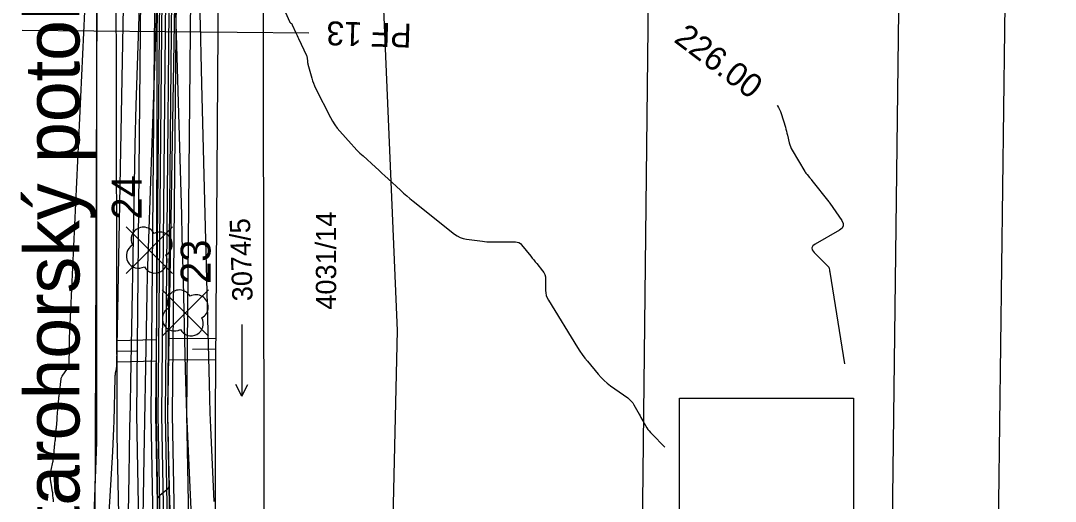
# Model space of a CAD drawing. Extents: x -534410 to -534262, y -1190162 to -1189584.
# Drawn here: x -534372.62 to -534329.29, y -1189850.35 to -1189830.22 of the extents above; entities that cross this region are included whole.
import ezdxf

# ---------------------------------------------------------------- set-up
doc = ezdxf.new("R2010")
doc.units = 0
for name, color, linetype in [('30', 7, 'Continuous'), ('31', 7, 'Continuous'), ('40', 7, 'Continuous'), ('_linie', 7, 'Continuous'), ('_N_osa', 7, 'Continuous'), ('_N_tenká', 7, 'Continuous'), ('_N_tenká_velmi', 7, 'Continuous'), ('_N_text', 7, 'Continuous'), ('_přístup', 7, 'Continuous'), ('_tenka', 7, 'Continuous'), ('_velmi_tenka', 7, 'Continuous'), ('Default', 7, 'Continuous'), ('Hranice parcel', 7, 'Continuous'), ('Parcelní čísla', 7, 'Continuous'), ('Pop  PČ popisy', 7, 'Continuous'), ('Značky kultur', 7, 'Continuous')]:
    doc.layers.add(name, color=color, linetype=linetype)

msp = doc.modelspace()

# ---------------------------------------------------------------- linework, layer by layer
at = {"layer": '30'}
for points in [[(-534371.244, -1189850.375), (-534371.248, -1189850.341), (-534371.252, -1189850.306), (-534371.255, -1189850.272), (-534371.258, -1189850.238), (-534371.271, -1189850.1), (-534371.275, -1189850.066), (-534371.279, -1189850.032), (-534371.284, -1189849.997), (-534371.29, -1189849.963), (-534371.354, -1189849.6), (-534371.361, -1189849.554), (-534371.366, -1189849.509), (-534371.369, -1189849.463), (-534371.369, -1189849.417), (-534371.367, -1189849.233), (-534371.366, -1189849.187), (-534371.362, -1189849.141), (-534371.356, -1189849.095), (-534371.347, -1189849.05), (-534371.276, -1189848.71), (-534371.269, -1189848.675), (-534371.263, -1189848.638), (-534371.258, -1189848.602), (-534371.253, -1189848.566), (-534371.238, -1189848.42), (-534371.234, -1189848.384), (-534371.23, -1189848.347), (-534371.227, -1189848.311), (-534371.224, -1189848.274), (-534371.205, -1189848.054), (-534371.202, -1189848.024), (-534371.199, -1189847.994), (-534371.195, -1189847.964), (-534371.191, -1189847.934), (-534371.174, -1189847.815), (-534371.17, -1189847.785), (-534371.166, -1189847.755), (-534371.163, -1189847.725), (-534371.161, -1189847.695), (-534371.143, -1189847.465), (-534371.139, -1189847.416), (-534371.136, -1189847.368), (-534371.132, -1189847.319), (-534371.128, -1189847.271), (-534371.101, -1189846.933), (-534371.1, -1189846.923), (-534371.1, -1189846.914), (-534371.099, -1189846.905), (-534371.099, -1189846.896), (-534371.1, -1189846.859), (-534371.1, -1189846.85), (-534371.099, -1189846.841), (-534371.099, -1189846.832), (-534371.098, -1189846.823), (-534371.067, -1189846.499), (-534371.061, -1189846.444), (-534371.056, -1189846.388), (-534371.051, -1189846.333), (-534371.046, -1189846.277), (-534371.02, -1189845.971), (-534371.019, -1189845.957), (-534371.017, -1189845.943), (-534371.015, -1189845.93), (-534371.013, -1189845.916), (-534371.002, -1189845.86), (-534371, -1189845.846), (-534370.998, -1189845.833), (-534370.996, -1189845.819), (-534370.994, -1189845.805), (-534370.96, -1189845.471), (-534370.957, -1189845.44), (-534370.953, -1189845.409), (-534370.949, -1189845.378), (-534370.945, -1189845.347), (-534370.928, -1189845.223), (-534370.922, -1189845.192), (-534370.913, -1189845.163), (-534370.9, -1189845.135), (-534370.884, -1189845.109), (-534370.661, -1189844.787), (-534370.635, -1189844.744), (-534370.616, -1189844.699), (-534370.604, -1189844.651), (-534370.599, -1189844.601), (-534370.59, -1189844.359), (-534370.588, -1189844.327), (-534370.588, -1189844.294), (-534370.587, -1189844.262), (-534370.586, -1189844.229), (-534370.584, -1189844.067), (-534370.583, -1189844.035), (-534370.583, -1189844.003), (-534370.581, -1189843.94), (-534370.58, -1189843.908), (-534370.579, -1189843.876), (-534370.577, -1189843.711), (-534370.576, -1189843.646), (-534370.575, -1189843.58), (-534370.573, -1189843.403), (-534370.573, -1189843.376), (-534370.572, -1189843.349), (-534370.571, -1189843.296), (-534370.571, -1189843.282), (-534370.57, -1189843.269), (-534370.57, -1189843.255), (-534370.569, -1189843.242), (-534369.518, -1189820.88)], [(-534369.971, -1189897.16), (-534368.36, -1189871.02), (-534368.275, -1189869.436), (-534368.214, -1189867.85), (-534368.178, -1189866.264), (-534368.167, -1189864.676), (-534368.175, -1189857.116), (-534368.173, -1189856.134), (-534368.168, -1189855.152), (-534368.158, -1189854.17), (-534368.144, -1189853.188), (-534368.08, -1189849.26), (-534368.063, -1189848.277), (-534368.046, -1189847.295), (-534368.029, -1189846.313), (-534368.011, -1189845.331), (-534367.857, -1189837.063), (-534367.823, -1189835.407), (-534367.782, -1189833.752), (-534367.734, -1189832.096), (-534367.679, -1189830.441), (-534367.447, -1189823.822)], [(-534365.145, -1189829.164), (-534365.111, -1189830.395), (-534365.079, -1189831.626), (-534365.048, -1189832.857), (-534364.733, -1189845.414), (-534364.716, -1189846.032), (-534364.696, -1189846.65), (-534364.672, -1189847.268), (-534364.645, -1189847.886), (-534364.532, -1189850.357)], [(-534340.948, -1189833.761), (-534340.933, -1189833.783), (-534340.884, -1189833.858), (-534340.841, -1189833.936), (-534340.805, -1189834.018), (-534340.776, -1189834.102), (-534340.597, -1189834.684), (-534340.573, -1189834.764), (-534340.551, -1189834.845), (-534340.53, -1189834.927), (-534340.51, -1189835.008), (-534340.436, -1189835.336), (-534340.414, -1189835.416), (-534340.386, -1189835.495), (-534340.352, -1189835.571), (-534340.312, -1189835.644), (-534339.784, -1189836.536), (-534339.763, -1189836.57), (-534339.74, -1189836.603), (-534339.716, -1189836.634), (-534339.691, -1189836.665), (-534339.587, -1189836.785), (-534339.561, -1189836.815), (-534339.536, -1189836.845), (-534339.511, -1189836.876), (-534339.486, -1189836.907), (-534338.782, -1189837.804), (-534338.768, -1189837.821), (-534338.754, -1189837.839), (-534338.747, -1189837.848), (-534338.74, -1189837.857), (-534338.233, -1189838.595), (-534338.174, -1189838.714), (-534338.17, -1189838.819), (-534338.22, -1189838.913), (-534338.324, -1189838.993), (-534339.35, -1189839.574), (-534339.448, -1189839.65), (-534339.489, -1189839.733), (-534339.472, -1189839.825), (-534339.397, -1189839.924), (-534338.809, -1189840.513), (-534338.795, -1189840.528), (-534338.784, -1189840.545), (-534338.776, -1189840.564), (-534338.77, -1189840.584), (-534338.754, -1189840.666), (-534338.75, -1189840.687), (-534338.746, -1189840.708), (-534338.742, -1189840.729), (-534338.739, -1189840.749), (-534338.124, -1189844.595)], [(-534364.785, -1189884.896), (-534366.41, -1189849.75), (-534366.411, -1189849.736), (-534366.415, -1189849.731), (-534366.419, -1189849.735), (-534366.426, -1189849.747), (-534366.455, -1189849.813), (-534366.463, -1189849.829), (-534366.473, -1189849.844), (-534366.484, -1189849.857), (-534366.498, -1189849.869), (-534366.792, -1189850.108), (-534366.839, -1189850.154), (-534366.873, -1189850.208), (-534366.894, -1189850.267), (-534366.902, -1189850.333), (-534367.168, -1189866.532), (-534367.207, -1189869.255), (-534367.234, -1189871.978), (-534367.249, -1189874.701), (-534367.252, -1189877.424), (-534367.219, -1189912.738)]]:
    msp.add_lwpolyline(points, dxfattribs=at)
at = {"layer": '31'}
for points in [[(-534364.093, -1189824.142), (-534361.369, -1189830.256), (-534361.362, -1189830.269), (-534361.354, -1189830.282), (-534361.344, -1189830.293), (-534361.333, -1189830.303), (-534361.284, -1189830.342), (-534361.273, -1189830.352), (-534361.263, -1189830.364), (-534361.254, -1189830.376), (-534361.247, -1189830.39), (-534361.098, -1189830.724), (-534361.071, -1189830.784), (-534361.044, -1189830.844), (-534361.016, -1189830.904), (-534360.988, -1189830.964), (-534360.656, -1189831.676), (-534360.644, -1189831.704), (-534360.635, -1189831.733), (-534360.629, -1189831.762), (-534360.625, -1189831.793), (-534360.616, -1189831.915), (-534360.612, -1189831.946), (-534360.608, -1189831.976), (-534360.602, -1189832.006), (-534360.595, -1189832.036), (-534360.434, -1189832.628), (-534360.402, -1189832.735), (-534360.365, -1189832.84), (-534360.322, -1189832.944), (-534360.273, -1189833.045), (-534359.648, -1189834.273), (-534359.563, -1189834.427), (-534359.468, -1189834.576), (-534359.365, -1189834.717), (-534359.252, -1189834.853), (-534358.781, -1189835.383), (-534358.662, -1189835.514), (-534358.539, -1189835.641), (-534358.413, -1189835.765), (-534358.284, -1189835.885), (-534357.76, -1189836.361), (-534357.629, -1189836.481), (-534357.499, -1189836.6), (-534357.369, -1189836.72), (-534357.239, -1189836.84), (-534356.722, -1189837.323), (-534356.591, -1189837.442), (-534356.458, -1189837.559), (-534356.323, -1189837.673), (-534356.186, -1189837.784), (-534354.456, -1189839.157), (-534354.341, -1189839.237), (-534354.218, -1189839.299), (-534354.088, -1189839.344), (-534353.95, -1189839.372), (-534353.281, -1189839.461), (-534353.192, -1189839.472), (-534353.102, -1189839.479), (-534353.013, -1189839.483), (-534352.923, -1189839.485), (-534352.464, -1189839.485), (-534352.223, -1189839.485), (-534351.903, -1189839.485), (-534351.827, -1189839.493), (-534351.758, -1189839.516), (-534351.697, -1189839.555), (-534351.643, -1189839.61), (-534351.261, -1189840.087), (-534351.2, -1189840.163), (-534351.138, -1189840.239), (-534351.076, -1189840.315), (-534351.013, -1189840.391), (-534350.763, -1189840.693), (-534350.709, -1189840.772), (-534350.67, -1189840.856), (-534350.646, -1189840.945), (-534350.638, -1189841.041), (-534350.638, -1189841.516), (-534350.631, -1189841.626), (-534350.609, -1189841.732), (-534350.573, -1189841.833), (-534350.521, -1189841.931), (-534349.301, -1189843.914), (-534349.206, -1189844.064), (-534349.105, -1189844.209), (-534348.999, -1189844.351), (-534348.888, -1189844.489), (-534348.432, -1189845.034), (-534348.315, -1189845.166), (-534348.189, -1189845.29), (-534348.056, -1189845.405), (-534347.916, -1189845.512), (-534347.202, -1189846.021), (-534347.124, -1189846.084), (-534347.054, -1189846.153), (-534346.992, -1189846.231), (-534346.939, -1189846.315), (-534346.725, -1189846.7), (-534346.685, -1189846.772), (-534346.644, -1189846.844), (-534346.603, -1189846.916), (-534346.562, -1189846.987), (-534346.396, -1189847.272), (-534346.352, -1189847.341), (-534346.304, -1189847.408), (-534346.252, -1189847.471), (-534346.196, -1189847.531), (-534345.645, -1189848.085)], [(-534371.625, -1189891.598), (-534370.83, -1189881.739), (-534370.701, -1189880.087), (-534370.581, -1189878.435), (-534370.47, -1189876.783), (-534370.367, -1189875.13), (-534368.767, -1189848.262), (-534368.749, -1189847.944), (-534368.734, -1189847.627), (-534368.723, -1189847.309), (-534368.714, -1189846.991), (-534368.672, -1189845.178), (-534368.67, -1189845.131), (-534368.666, -1189845.084), (-534368.659, -1189845.038), (-534368.651, -1189844.991), (-534368.615, -1189844.806), (-534368.607, -1189844.76), (-534368.601, -1189844.714), (-534368.597, -1189844.667), (-534368.595, -1189844.62), (-534368.288, -1189828.137)], [(-534364.605, -1189869.948), (-534365.584, -1189848.548), (-534365.624, -1189847.62), (-534365.659, -1189846.693), (-534365.689, -1189845.766), (-534365.715, -1189844.838), (-534365.808, -1189841.128), (-534365.831, -1189840.2), (-534365.856, -1189839.273), (-534365.881, -1189838.345), (-534365.907, -1189837.418), (-534366.164, -1189828.418)], [(-534366.924, -1189829.286), (-534367.277, -1189839.352), (-534367.303, -1189840.115), (-534367.325, -1189840.877), (-534367.343, -1189841.64), (-534367.359, -1189842.403), (-534367.416, -1189845.454), (-534367.43, -1189846.216), (-534367.444, -1189846.979), (-534367.457, -1189847.742), (-534367.469, -1189848.505), (-534367.649, -1189859.418), (-534367.678, -1189861.492), (-534367.699, -1189863.565), (-534367.71, -1189865.638), (-534367.713, -1189867.712), (-534367.696, -1189886.193), (-534367.71, -1189888.284), (-534367.757, -1189890.373)]]:
    msp.add_lwpolyline(points, dxfattribs=at)
at = {"layer": '_linie'}
for points in [[(-534366.12, -1189620.81), (-534364.52, -1189627.2), (-534365.69, -1189653.8), (-534366.76, -1189684.81), (-534368.14, -1189748.73), (-534368.38, -1189779.14), (-534368.65, -1189820.64), (-534368.59, -1189847.58), (-534367.2, -1189913.8)], [(-534363.12, -1189621.02), (-534362.79, -1189621.58), (-534361.82, -1189627.79), (-534363.46, -1189653.55), (-534365.47, -1189684.77), (-534366.65, -1189748.83), (-534366.75, -1189779.47), (-534366.9, -1189820.47), (-534366.95, -1189846.72), (-534366.338, -1189888.804), (-534363.85, -1189911.95), (-534357.07, -1189929.19), (-534352.334, -1189940.856)], [(-534359.03, -1189621.26), (-534359.41, -1189621.83), (-534360.84, -1189627.76), (-534362.92, -1189653.56), (-534364.64, -1189685), (-534365.94, -1189748.9), (-534366.02, -1189779.52), (-534366.03, -1189820.5), (-534366.48, -1189846.73), (-534365.511, -1189888.873), (-534362.72, -1189912.12), (-534356.62, -1189928.64), (-534351.589, -1189940.594)]]:
    msp.add_lwpolyline(points, dxfattribs=at)
at = {"layer": '_N_osa'}
msp.add_lwpolyline([(-534351.95, -1189940.722), (-534356.845, -1189928.915), (-534363.285, -1189912.035), (-534365.925, -1189888.838), (-534366.715, -1189846.725), (-534366.465, -1189820.485), (-534366.385, -1189779.495), (-534366.295, -1189748.865), (-534365.055, -1189684.885), (-534363.19, -1189653.555), (-534361.333, -1189627.822)], dxfattribs=at)
at = {"layer": '_N_tenká'}
for points in [[(-534352.92, -1189941.124), (-534357.821, -1189929.303), (-534364.313, -1189912.285), (-534366.973, -1189888.908), (-534367.765, -1189846.73), (-534367.515, -1189820.479), (-534367.435, -1189779.492), (-534367.345, -1189748.853), (-534366.104, -1189684.844), (-534364.238, -1189653.486), (-534362.424, -1189628.352), (-534361.782, -1189627.792)], [(-534350.98, -1189940.319), (-534355.869, -1189928.527), (-534362.257, -1189911.785), (-534364.876, -1189888.769), (-534365.665, -1189846.72), (-534365.415, -1189820.491), (-534365.335, -1189779.498), (-534365.245, -1189748.877), (-534364.006, -1189684.926), (-534362.142, -1189653.624), (-534360.329, -1189628.488), (-534360.884, -1189627.851)]]:
    msp.add_lwpolyline(points, dxfattribs=at)
at = {"layer": '_N_tenká_velmi'}
for points in [[(-534352.366, -1189940.894), (-534357.263, -1189929.081), (-534363.726, -1189912.142), (-534366.374, -1189888.868), (-534367.165, -1189846.727), (-534366.915, -1189820.482), (-534366.835, -1189779.494), (-534366.745, -1189748.86), (-534365.505, -1189684.867), (-534363.639, -1189653.525), (-534361.782, -1189627.792)], [(-534352.181, -1189940.817), (-534357.077, -1189929.007), (-534363.53, -1189912.095), (-534366.174, -1189888.855), (-534366.965, -1189846.726), (-534366.715, -1189820.484), (-534366.635, -1189779.494), (-534366.545, -1189748.862), (-534365.305, -1189684.875), (-534363.439, -1189653.539), (-534361.583, -1189627.805)], [(-534352.089, -1189940.779), (-534356.984, -1189928.97), (-534363.432, -1189912.071), (-534366.074, -1189888.848), (-534366.865, -1189846.726), (-534366.615, -1189820.484), (-534366.535, -1189779.495), (-534366.445, -1189748.863), (-534365.205, -1189684.879), (-534363.34, -1189653.545), (-534361.483, -1189627.812)], [(-534351.812, -1189940.664), (-534356.706, -1189928.86), (-534363.138, -1189911.999), (-534365.775, -1189888.828), (-534366.565, -1189846.724), (-534366.315, -1189820.486), (-534366.235, -1189779.495), (-534366.145, -1189748.867), (-534364.905, -1189684.891), (-534363.04, -1189653.565), (-534361.184, -1189627.831)], [(-534351.719, -1189940.626), (-534356.613, -1189928.823), (-534363.04, -1189911.975), (-534365.675, -1189888.822), (-534366.465, -1189846.724), (-534366.215, -1189820.486), (-534366.135, -1189779.496), (-534366.045, -1189748.868), (-534364.805, -1189684.895), (-534362.941, -1189653.571), (-534361.084, -1189627.838)], [(-534351.534, -1189940.549), (-534356.427, -1189928.749), (-534362.844, -1189911.928), (-534365.475, -1189888.808), (-534366.265, -1189846.723), (-534366.015, -1189820.488), (-534365.935, -1189779.496), (-534365.845, -1189748.87), (-534364.605, -1189684.903), (-534362.741, -1189653.585), (-534360.884, -1189627.851)]]:
    msp.add_lwpolyline(points, dxfattribs=at)
at = {"layer": '_N_text'}
msp.add_lwpolyline([(-534360.562, -1189830.746), (-534372.562, -1189830.632)], dxfattribs=at)
msp.add_lwpolyline([(-534345.025, -1189888.22), (-534345.025, -1189846.037), (-534337.749, -1189846.037), (-534337.749, -1189888.22)], close=True, dxfattribs=at)
at = {"layer": '_přístup'}
for p, q in [((-534366.267, -1189840.803), (-534368.213, -1189838.857)), ((-534368.213, -1189840.803), (-534366.267, -1189838.857)), ((-534364.757, -1189843.433), (-534366.703, -1189841.487)), ((-534366.703, -1189843.433), (-534364.757, -1189841.487))]:
    msp.add_line(p, q, dxfattribs=at)
for centre in [(-534367.24, -1189839.83), (-534365.73, -1189842.46)]:
    msp.add_circle(centre, 0.000512, dxfattribs=at)
for centre, start, end in [((-534367.485, -1189839.381), 28.6209, 208.6209), ((-534366.791, -1189839.585), 298.6209, 118.6209), ((-534367.689, -1189840.075), 118.6209, 298.6209), ((-534366.995, -1189840.279), 208.6209, 28.6209), ((-534365.975, -1189842.011), 28.6209, 208.6209), ((-534365.281, -1189842.215), 298.6209, 118.6209), ((-534366.179, -1189842.705), 118.6209, 298.6209), ((-534365.485, -1189842.909), 208.6209, 28.6209)]:
    msp.add_arc(centre, 0.512, start, end, dxfattribs=at)
at = {"layer": '_tenka'}
for points in [[(-534349.13, -1189939.73), (-534354.63, -1189926.96), (-534362.03, -1189907.65), (-534364.521, -1189888.74), (-534364.47, -1189846.64), (-534364.29, -1189820.63), (-534364.22, -1189780.69), (-534363.18, -1189749.38), (-534362.5, -1189685.39), (-534360.27, -1189651.6), (-534357.03, -1189627.34), (-534354.77, -1189620.37)], [(-534366.12, -1189620.81), (-534364.52, -1189627.2), (-534365.69, -1189653.8), (-534366.76, -1189684.81), (-534368.14, -1189748.73), (-534368.38, -1189779.14), (-534368.65, -1189820.64), (-534368.59, -1189847.58), (-534367.2, -1189913.8)], [(-534366.12, -1189620.81), (-534364.52, -1189627.2), (-534365.69, -1189653.8), (-534366.76, -1189684.81), (-534368.14, -1189748.73), (-534368.38, -1189779.14), (-534368.65, -1189820.64), (-534368.59, -1189847.58), (-534367.2, -1189913.8)], [(-534363.12, -1189621.02), (-534362.79, -1189621.58), (-534361.82, -1189627.79), (-534363.46, -1189653.55), (-534365.47, -1189684.77), (-534366.65, -1189748.83), (-534366.75, -1189779.47), (-534366.9, -1189820.47), (-534366.95, -1189846.72), (-534366.338, -1189888.804), (-534363.85, -1189911.95), (-534357.07, -1189929.19), (-534352.334, -1189940.856)], [(-534363.12, -1189621.02), (-534362.79, -1189621.58), (-534361.82, -1189627.79), (-534363.46, -1189653.55), (-534365.47, -1189684.77), (-534366.65, -1189748.83), (-534366.75, -1189779.47), (-534366.9, -1189820.47), (-534366.95, -1189846.72), (-534366.338, -1189888.804), (-534363.85, -1189911.95), (-534357.07, -1189929.19), (-534352.334, -1189940.856)], [(-534359.03, -1189621.26), (-534359.41, -1189621.83), (-534360.84, -1189627.76), (-534362.92, -1189653.56), (-534364.64, -1189685), (-534365.94, -1189748.9), (-534366.02, -1189779.52), (-534366.03, -1189820.5), (-534366.48, -1189846.73), (-534365.511, -1189888.873), (-534362.72, -1189912.12), (-534356.62, -1189928.64), (-534351.589, -1189940.594)], [(-534359.03, -1189621.26), (-534359.41, -1189621.83), (-534360.84, -1189627.76), (-534362.92, -1189653.56), (-534364.64, -1189685), (-534365.94, -1189748.9), (-534366.02, -1189779.52), (-534366.03, -1189820.5), (-534366.48, -1189846.73), (-534365.511, -1189888.873), (-534362.72, -1189912.12), (-534356.62, -1189928.64), (-534351.589, -1189940.594)], [(-534368.65, -1189626.81), (-534368.65, -1189626.81), (-534367.31, -1189654.04), (-534367.67, -1189685.23), (-534369.56, -1189748.93), (-534369.48, -1189778.6), (-534369.45, -1189820.62), (-534369.45, -1189847.87), (-534371.206, -1189896.071), (-534372.39, -1189914.47)]]:
    msp.add_lwpolyline(points, dxfattribs=at)
at = {"layer": '_velmi_tenka'}
for p, q in [((-534364.455, -1189843.532), (-534366.402, -1189843.546)), ((-534368.609, -1189843.616), (-534366.956, -1189843.574)), ((-534364.452, -1189843.982), (-534365.425, -1189843.989)), ((-534368.598, -1189844.066), (-534367.771, -1189844.045)), ((-534364.448, -1189844.432), (-534366.396, -1189844.446)), ((-534368.586, -1189844.516), (-534366.933, -1189844.473))]:
    msp.add_line(p, q, dxfattribs=at)
at = {"layer": 'Default'}
msp.add_line((-534369.45, -1189820.62), (-534369.45, -1189847.87), dxfattribs=at)
msp.add_lwpolyline([(-534349.13, -1189939.73), (-534354.63, -1189926.96), (-534362.03, -1189907.65), (-534364.521, -1189888.74), (-534364.47, -1189846.64), (-534364.29, -1189820.63), (-534364.22, -1189780.69), (-534363.18, -1189749.38), (-534362.5, -1189685.39), (-534360.27, -1189651.6), (-534357.03, -1189627.34), (-534354.77, -1189620.37)], dxfattribs=at)
at = {"layer": 'Hranice parcel'}
msp.add_line((-534369.75, -1189908.47), (-534369.38, -1189820.8), dxfattribs=at)
for points in [[(-534347.07, -1189935.15), (-534347.12, -1189900.1), (-534346.3, -1189826.77), (-534344.77, -1189736.43), (-534342.85, -1189658.07), (-534338.334, -1189584.47)], [(-534338.84, -1189942.48), (-534336.49, -1189881.83), (-534334.78, -1189743.85), (-534331.25, -1189619.05), (-534329.563, -1189584.47)], [(-534334.89, -1189942.46), (-534332.03, -1189880.06), (-534330.32, -1189744.92), (-534329.292, -1189689.47)], [(-534359.48, -1189697.97), (-534362.6, -1189764.35), (-534362.34, -1189901.56)], [(-534359.48, -1189697.97), (-534360.42, -1189747.8), (-534359.17, -1189788.69), (-534356.86, -1189843.2), (-534358.53, -1189915.98)]]:
    msp.add_lwpolyline(points, dxfattribs=at)
at = {"layer": 'Značky kultur'}
for p, q in [((-534363.36, -1189842.944), (-534363.36, -1189845.944)), ((-534363.36, -1189845.944), (-534363.611, -1189845.455)), ((-534363.36, -1189845.944), (-534363.109, -1189845.455))]:
    msp.add_line(p, q, dxfattribs=at)

# ---------------------------------------------------------------- texts
at = {"layer": '40'}
msp.add_text('226.00', height=1, rotation=322.9354, dxfattribs=at).set_placement((-534345.311, -1189831.072))
at = {"layer": '_N_text'}
msp.add_text('PF 13', height=1, rotation=178.2752, dxfattribs=at).set_placement((-534356.235, -1189830.349))
at = {"layer": '_přístup'}
for s, p in [('24', (-534367.557, -1189838.551)), ('23', (-534364.674, -1189841.248))]:
    msp.add_text(s, height=1.25, rotation=90, dxfattribs=at).set_placement(p)
at = {"layer": 'Parcelní čísla'}
for s, rotation, p in [('4031/14', 90, (-534359.411, -1189842.326)), ('3074/5', 92, (-534362.905, -1189841.957))]:
    msp.add_text(s, height=0.85, rotation=rotation, dxfattribs=at).set_placement(p)
at = {"layer": 'Pop  PČ popisy'}
msp.add_text('Starohorský potok', height=2.3, rotation=90, dxfattribs=at).set_placement((-534370.162, -1189853.443))

doc.saveas('drawing.dxf')
